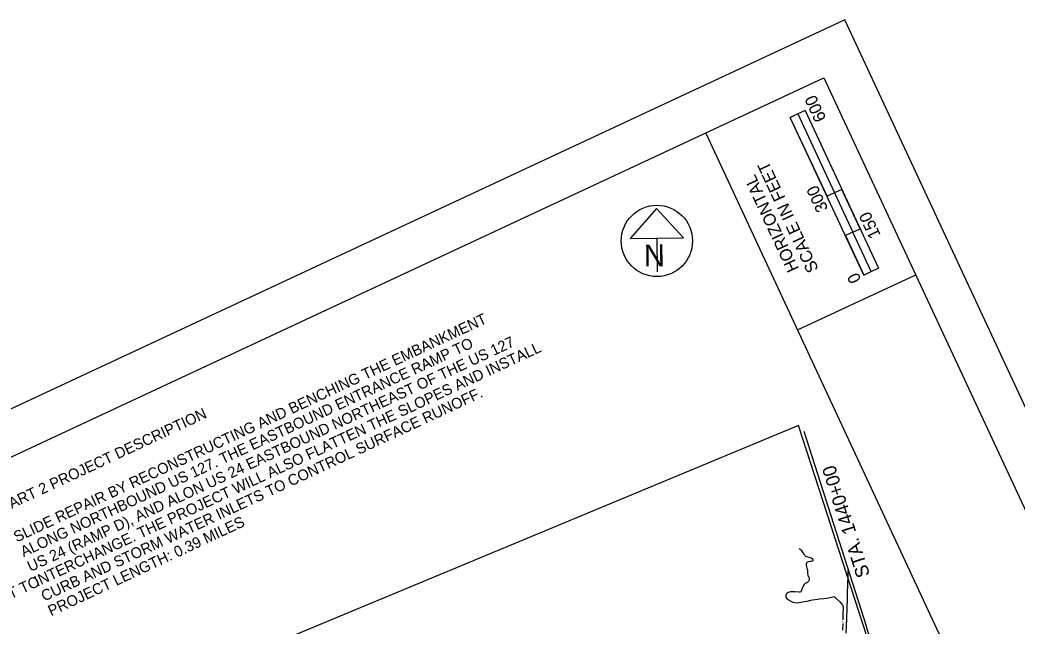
# Model space of a CAD drawing. Extents: x -310467766 to 17062430, y -322263100 to 8322522.
# Drawn here: x 1397865 to 1401306, y 576598 to 578688 of the extents above; entities that cross this region are included whole.
import ezdxf

# ---------------------------------------------------------------- set-up
doc = ezdxf.new("R2010")
doc.units = 0
for name, color, linetype in [('DT_X_Contour_Minor', 7, 'Continuous'), ('DT_X_Terrain_Ground_Line', 7, 'Continuous'), ('Level 19', 7, 'Continuous'), ('Level 40', 7, 'Continuous'), ('SC_Scratch1', 7, 'Continuous'), ('SH_Border', 7, 'Continuous'), ('SH_Cut_Line', 7, 'Continuous'), ('SH_Data', 7, 'Continuous'), ('SH_Masking', 7, 'Continuous'), ('SH_Text', 7, 'Continuous')]:
    doc.layers.add(name, color=color, linetype=linetype)

msp = doc.modelspace()

# ---------------------------------------------------------------- linework, layer by layer
at = {"layer": 'DT_X_Contour_Minor'}
for points in [[(1400585.8, 576770.2), (1400585.4, 576774.9), (1400584.7, 576780), (1400583.8, 576789.4), (1400582.9, 576793.3), (1400580.5, 576801.9), (1400579.8, 576807.6), (1400580.2, 576813.3), (1400582.4, 576817.8), (1400586.7, 576820.4), (1400592.1, 576821.5), (1400597.1, 576822), (1400600.4, 576822.8), (1400602.3, 576823.8), (1400603, 576824.8), (1400603.1, 576825.6), (1400602.1, 576827.1), (1400600.3, 576828.7), (1400596, 576831.6), (1400592.6, 576833.3), (1400588.6, 576834.7), (1400580.3, 576836.4), (1400576.8, 576838.2), (1400574.4, 576841.3), (1400572, 576845.6), (1400568.7, 576850.8), (1400563.7, 576856.6), (1400557.6, 576862.2), (1400554.5, 576864.6)], [(1400585.8, 576770.2), (1400586.3, 576769.3), (1400587.9, 576764.8), (1400588.8, 576760.4), (1400588.6, 576756.5), (1400587.5, 576753.4), (1400585.9, 576750.8), (1400583.9, 576748.7), (1400581.9, 576747.2), (1400579.9, 576746.3), (1400576.4, 576745.1), (1400574.4, 576743.7), (1400572.2, 576741), (1400569.9, 576737.5), (1400566.1, 576730.6), (1400563.8, 576724.5), (1400562.8, 576721.3), (1400561.5, 576718.3), (1400559.6, 576716.1), (1400556.9, 576715.1), (1400553.4, 576715), (1400540, 576715.5), (1400524.4, 576715.8), (1400520.6, 576715.1), (1400516.6, 576713.7), (1400512.8, 576711.4), (1400509.6, 576708.1), (1400507.9, 576703.9), (1400508.5, 576698.8), (1400512.1, 576693.1), (1400518, 576687.6), (1400525.1, 576683.1), (1400532.2, 576680.3), (1400538.7, 576678.9), (1400547.2, 576678.3), (1400552.7, 576678.9), (1400573.1, 576681.8), (1400581.7, 576683.8), (1400594.9, 576687.5), (1400599.9, 576688.6), (1400609.8, 576689.8), (1400618.1, 576690.8), (1400624.7, 576691.7), (1400639.4, 576692.5), (1400651.3, 576694.4), (1400670.6, 576698.6), (1400674.8, 576699.4), (1400675.3, 576699.2), (1400681.4, 576693.4), (1400694.6, 576680.7), (1400700.6, 576674.4), (1400704, 576669.9), (1400705.3, 576667), (1400705.7, 576663.5), (1400705.4, 576636.9), (1400705.1, 576618.9)], [(1400716.5, 576573.2), (1400717.6, 576597.9), (1400718.7, 576625.4), (1400720.1, 576659.7), (1400721, 576692.6), (1400721.7, 576712.7), (1400722.5, 576738.9), (1400723.3, 576774.6), (1400723.9, 576789.8)], [(1400704.9, 576606.9), (1400704.4, 576583.5)]]:
    msp.add_lwpolyline(points, dxfattribs=at)
at = {"layer": 'DT_X_Terrain_Ground_Line'}
for p in [(1400570.1, 577269.8), (1401011.3, 575892.5)]:
    msp.add_line(p, (1400785.1, 576598.8), dxfattribs=at)
at = {"layer": 'SC_Scratch1'}
msp.add_lwpolyline([(1392212.4, 573822.1), (1393676.3, 570715.4), (1396857.5, 571041.4), (1399761.2, 572912.7), (1399601.4, 573251.9), (1400998.4, 575913.7), (1400551.7, 577289.3)], close=True, dxfattribs=at)
at = {"layer": 'SH_Border'}
for p, q in [((1402894.4, 572589.2), (1400231.9, 578298.9)), ((1400548.9, 577619.2), (1400956.7, 577809.4))]:
    msp.add_line(p, q, dxfattribs=at)
msp.add_lwpolyline([(1391939.2, 574432), (1400639.7, 578489.1), (1403302.2, 572779.4), (1394601.7, 568722.3)], close=True, dxfattribs=at)
at = {"layer": 'SH_Cut_Line'}
msp.add_lwpolyline([(1394257.2, 568396.1), (1403501.6, 572706.8), (1400712.3, 578688.5), (1391467.9, 574377.8)], close=True, dxfattribs=at)
at = {"layer": 'SH_Data'}
for p, q in [((1400574.7, 578376), (1400523.7, 578352.3)), ((1400523.7, 578352.3), (1400549.1, 578364.1)), ((1400777.3, 577808.5), (1400523.7, 578352.3)), ((1400650.5, 578080.4), (1400523.7, 578352.3)), ((1400549.1, 578364.1), (1400549.3, 578364.2)), ((1400549.3, 578364.2), (1400676.1, 578092.3)), ((1400574.7, 578376), (1400828.3, 577832.3)), ((1400676.1, 578092.3), (1400650.5, 578080.4)), ((1400701.2, 578104), (1400675.9, 578092.2)), ((1400675.9, 578092.2), (1400739.3, 577956.3)), ((1400764.6, 577968.1), (1400701.2, 578104)), ((1400739.3, 577956.3), (1400713.9, 577944.4)), ((1400713.9, 577944.4), (1400777.3, 577808.5)), ((1400739.3, 577956.3), (1400764.6, 577968.1)), ((1400802.6, 577820.3), (1400739.3, 577956.3)), ((1400828.3, 577832.3), (1400777.3, 577808.5)), ((1400777.3, 577808.5), (1400802.6, 577820.3))]:
    msp.add_line(p, q, dxfattribs=at)
at = {"layer": 'SH_Masking'}
msp.add_circle((1400063.3, 577926.2), 123, dxfattribs=at)
at = {"layer": 'SH_Text'}
for p, q in [((1400062, 578038.3), (1399970.9, 577934.9)), ((1400155.4, 577937), (1400062, 578038.3)), ((1399970.9, 577934.9), (1400155.4, 577937)), ((1400063.2, 577936), (1400064.5, 577819.9))]:
    msp.add_line(p, q, dxfattribs=at)
msp.add_circle((1400063.3, 577926.2), 123, dxfattribs=at)

# ---------------------------------------------------------------- texts
at = {"layer": 'DT_X_Terrain_Ground_Line'}
msp.add_text('STA. 1440+00', height=46.8, rotation=107.7616, dxfattribs=at).set_placement((1400799.5, 576773.4))
at = {"layer": 'Level 19'}
msp.add_text('716', height=4, rotation=88.734, dxfattribs=at).set_placement((1400706.9, 576607.5))
at = {"layer": 'Level 40'}
for s, p in [('SLIDE REPAIR BY RECONSTRUCTING AND BENCHING THE EMBANKMENT', (1397853.9, 576885.8)), ('US 24 (RAMP D), AND ALON US 24 EASTBOUND NORTHEAST OF THE US 127', (1397901.4, 576783.8)), ('ALONG NORTHBOUND US 127. THE EASTBOUND ENTRANCE RAMP TO', (1397877.7, 576834.8)), ('INTERCHANGE. THE PROJECT WILL ALSO FLATTEN THE SLOPES AND INSTALL', (1397925.2, 576732.9)), ('CURB AND STORM WATER INLETS TO CONTROL SURFACE RUNOFF.', (1397949, 576681.9)), ('PART 2 PROJECT DESCRIPTION', (1397806.3, 576987.8)), ('PROJECT LENGTH: 0.39 MILES', (1397972.7, 576630.9)), ('THE PROJECT ALSO INCLUDES AREAS OF FULL DEPTH PAVEMENT REPLACEMENT TO', (1396020.4, 575844.6))]:
    msp.add_text(s, height=37.5, rotation=25, dxfattribs=at).set_placement(p)
at = {"layer": 'SH_Data'}
for s, p in [('600', (1400649.1, 578348.5)), ('SCALE IN FEET', (1400622.5, 577828.7)), ('HORIZONTAL', (1400554.6, 577830.5)), ('300', (1400655.4, 578037)), ('150', (1400836.7, 577946.2)), ('0', (1400769.6, 577792.1))]:
    msp.add_text(s, height=42, rotation=115, dxfattribs=at).set_placement(p)
at = {"layer": 'SH_Text'}
msp.add_text('N', height=75, rotation=0.6369, dxfattribs=at).set_placement((1400018.9, 577838.3))

doc.saveas('drawing.dxf')
